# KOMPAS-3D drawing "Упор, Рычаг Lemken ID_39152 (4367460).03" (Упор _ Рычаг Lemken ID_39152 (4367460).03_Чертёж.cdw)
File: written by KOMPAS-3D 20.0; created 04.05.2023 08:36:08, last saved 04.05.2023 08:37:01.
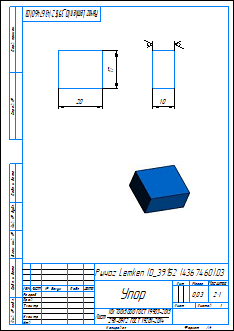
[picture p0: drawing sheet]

Sheet 1: A4, portrait

Document properties: Автор: factory; Масса: 0.02669

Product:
- Part/product: Упор  | designation Рычаг Lemken ID_39152 (4367460).03
    Материал: Лист$d10х700х5000 ГОСТ 19903-2015;295-09Г2 ГОСТ 19281-2014$ (density 7850 kg/m3)
    Масса: 0.02669
    source file: Упор _ Рычаг Lemken ID_39152 (4367460).03_Чертёж.cdw

Title block, sheet 1: Наименование: Упор; designation: Рычаг Lemken ID_39152 (4367460).03; Материал: Лист 10х700х5000 ГОСТ 19903-2015 295-09Г2 ГОСТ 19281-2014; Масса: 0,03; Количество листов документа: 1; Форматы листов документа: A4; stored path: C:\Users\factory\Desktop\Чертежи\Рычаг Lemken ID_39152 (4367460)\Упор _ Рычаг Lemken ID_39152 (4367460).03_Чертёж.cdw

Views: Вид 1, Спереди, Проекционный вид 2
Referenced files in C:\Users\factory\Desktop\Чертежи\Рычаг Lemken ID_39152 (4367460)\: Упор _ Рычаг Lemken ID_39152 (4367460).03.m3d, Упор _ Рычаг Lemken ID_39152 (4367460).03_Рис.jpg
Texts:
  Упор _ Рычаг Lemken ID_39152 (4367460).03_Рис.jpg
  Рычаг Lemken ID_39152 (4367460).03 Упор
Dimensions and other numbers on the sheet: 20; 17; 10; 2:1; 1; 0,03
